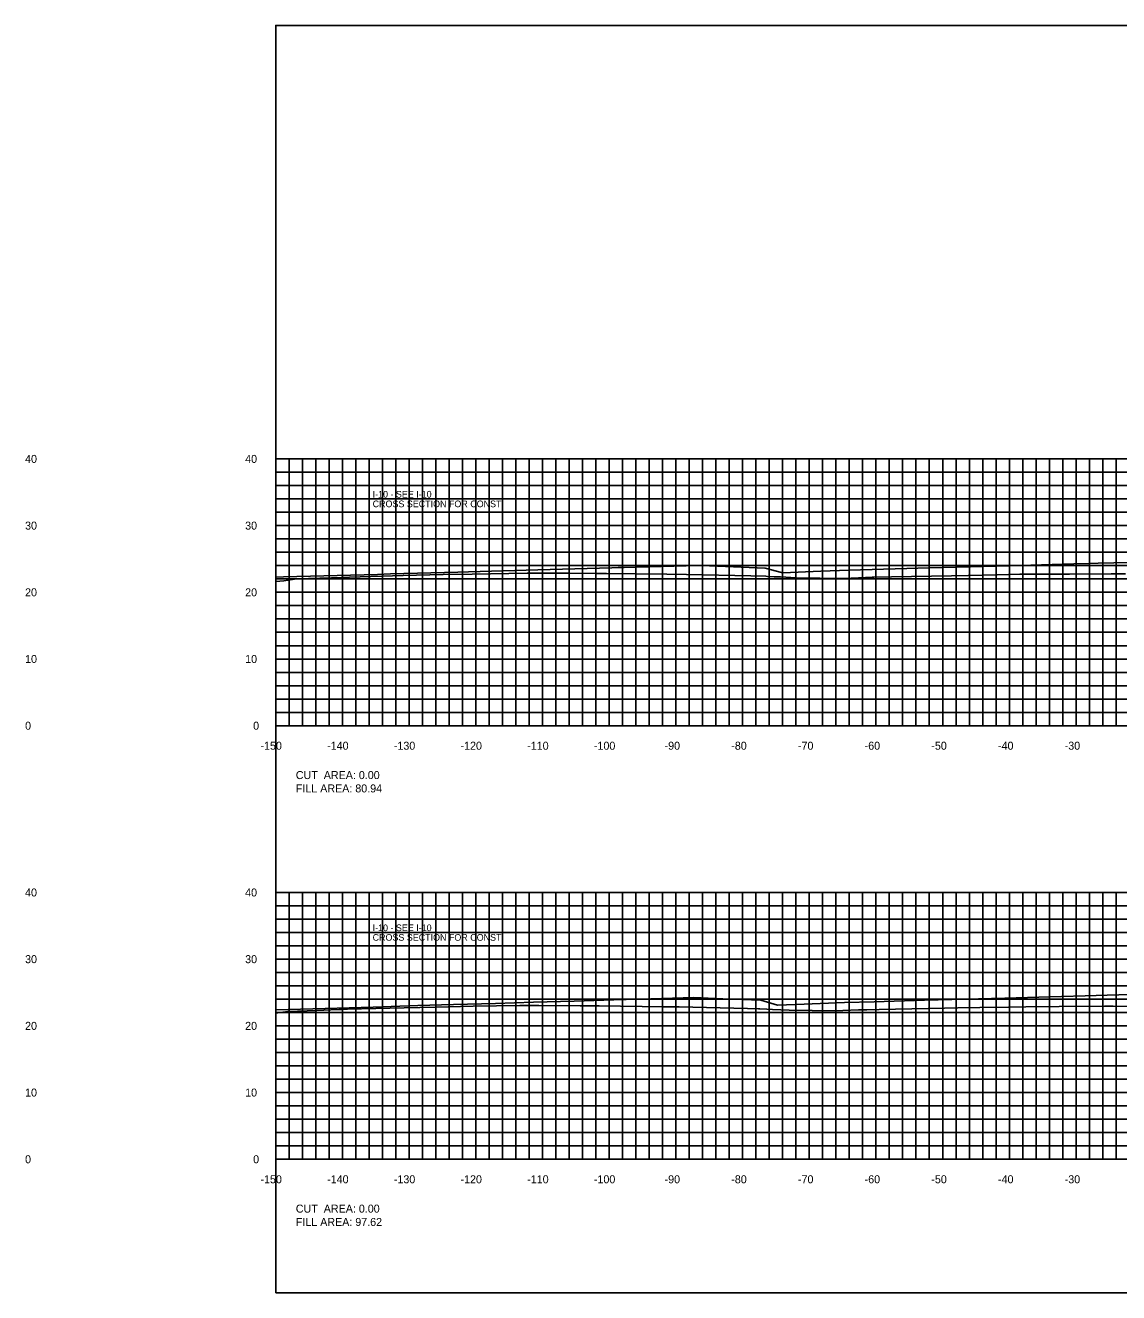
# Model space of a CAD drawing. Extents: x 1797652 to 1804145, y 245981 to 250269.
# Drawn here: x 1803803.4 to 1803967.4, y 250079.4 to 250269.4 of the extents above; entities that cross this region are included whole.
import ezdxf

# ---------------------------------------------------------------- set-up
doc = ezdxf.new("R2010")
doc.units = 0
for name, color, linetype in [('10', 7, 'Continuous'), ('3', 7, 'Continuous'), ('31', 7, 'Continuous'), ('60', 7, 'Continuous'), ('ANNO-TXT', 7, 'Continuous'), ('CL-CNST', 7, 'Continuous'), ('Level 62', 7, 'Continuous'), ('M-ROADS', 7, 'Continuous')]:
    doc.layers.add(name, color=color, linetype=linetype)

msp = doc.modelspace()

# ---------------------------------------------------------------- linework, layer by layer
msp.add_lwpolyline([(1803841, 250079.43), (1804141, 250079.43), (1804141, 250269.43), (1803841, 250269.43)], close=True)
at = {"layer": '60'}
for p, q in [((1803840.94, 250204.43), (1803841, 250204.43)), ((1803841, 250164.43), (1803841, 250204.43)), ((1803840.94, 250194.43), (1803841, 250194.43)), ((1803840.94, 250184.43), (1803841, 250184.43)), ((1803840.94, 250174.43), (1803841, 250174.43)), ((1803840.94, 250164.43), (1803841, 250164.43)), ((1803841, 250164.43), (1804141, 250164.43)), ((1803841, 250164.37), (1803841, 250164.43)), ((1803851, 250164.37), (1803851, 250164.43)), ((1803861, 250164.37), (1803861, 250164.43)), ((1803871, 250164.37), (1803871, 250164.43)), ((1803881, 250164.37), (1803881, 250164.43)), ((1803891, 250164.37), (1803891, 250164.43)), ((1803901, 250164.37), (1803901, 250164.43)), ((1803911, 250164.37), (1803911, 250164.43)), ((1803921, 250164.37), (1803921, 250164.43)), ((1803931, 250164.37), (1803931, 250164.43)), ((1803941, 250164.37), (1803941, 250164.43)), ((1803951, 250164.37), (1803951, 250164.43)), ((1803961, 250164.37), (1803961, 250164.43)), ((1803840.94, 250139.43), (1803841, 250139.43)), ((1803841, 250099.43), (1803841, 250139.43)), ((1803840.94, 250129.43), (1803841, 250129.43)), ((1803840.94, 250119.43), (1803841, 250119.43)), ((1803840.94, 250109.43), (1803841, 250109.43)), ((1803840.94, 250099.43), (1803841, 250099.43)), ((1803841, 250099.43), (1804141, 250099.43)), ((1803841, 250099.37), (1803841, 250099.43)), ((1803851, 250099.37), (1803851, 250099.43)), ((1803861, 250099.37), (1803861, 250099.43)), ((1803871, 250099.37), (1803871, 250099.43)), ((1803881, 250099.37), (1803881, 250099.43)), ((1803891, 250099.37), (1803891, 250099.43)), ((1803901, 250099.37), (1803901, 250099.43)), ((1803911, 250099.37), (1803911, 250099.43)), ((1803921, 250099.37), (1803921, 250099.43)), ((1803931, 250099.37), (1803931, 250099.43)), ((1803941, 250099.37), (1803941, 250099.43)), ((1803951, 250099.37), (1803951, 250099.43)), ((1803961, 250099.37), (1803961, 250099.43))]:
    msp.add_line(p, q, dxfattribs=at)
at = {"layer": 'CL-CNST'}
for points in [[(1803841, 250186.69), (1803842.17, 250186.73), (1803856.27, 250187.12), (1803858.22, 250187.18), (1803868.29, 250187.46), (1803869.89, 250187.51), (1803880.31, 250187.8), (1803891.39, 250188.11), (1803892.34, 250188.14), (1803893.23, 250188.17), (1803904.36, 250188.47), (1803904.81, 250188.45), (1803914.38, 250188.06), (1803916.85, 250187.38), (1803916.89, 250187.36), (1803917.03, 250187.37), (1803922.74, 250187.59), (1803926.91, 250187.75), (1803935.63, 250188), (1803938.93, 250188.09), (1803945.19, 250188.26), (1803950.95, 250188.41), (1803960.69, 250188.68), (1803962.98, 250188.74), (1803964.33, 250188.78), (1803969, 250188.9)], [(1803841, 250121.82), (1803848.41, 250122.05), (1803855.6, 250122.25), (1803862.29, 250122.46), (1803867.63, 250122.61), (1803873.94, 250122.8), (1803879.66, 250122.96), (1803885.76, 250123.13), (1803891.68, 250123.31), (1803897.24, 250123.48), (1803903.71, 250123.66), (1803908.05, 250123.49), (1803913.73, 250123.26), (1803915.21, 250122.85), (1803916.24, 250122.52), (1803920.24, 250122.68), (1803926.26, 250122.91), (1803930.72, 250123.05), (1803938.29, 250123.26), (1803942.37, 250123.38), (1803950.32, 250123.6), (1803958.8, 250123.83), (1803962.35, 250123.94), (1803965.67, 250124.04), (1803974.37, 250124.28)]]:
    msp.add_lwpolyline(points, dxfattribs=at)
at = {"layer": 'Level 62'}
for p, q in [((1803841, 250204.43), (1804141, 250204.43)), ((1803841, 250164.43), (1803841, 250204.43)), ((1803843, 250164.43), (1803843, 250204.43)), ((1803845, 250164.43), (1803845, 250204.43)), ((1803847, 250164.43), (1803847, 250204.43)), ((1803849, 250164.43), (1803849, 250204.43)), ((1803851, 250164.43), (1803851, 250204.43)), ((1803853, 250164.43), (1803853, 250204.43)), ((1803855, 250164.43), (1803855, 250204.43)), ((1803857, 250164.43), (1803857, 250204.43)), ((1803859, 250164.43), (1803859, 250204.43)), ((1803861, 250164.43), (1803861, 250204.43)), ((1803863, 250164.43), (1803863, 250204.43)), ((1803865, 250164.43), (1803865, 250204.43)), ((1803867, 250164.43), (1803867, 250204.43)), ((1803869, 250164.43), (1803869, 250204.43)), ((1803871, 250164.43), (1803871, 250204.43)), ((1803873, 250164.43), (1803873, 250204.43)), ((1803875, 250164.43), (1803875, 250204.43)), ((1803877, 250164.43), (1803877, 250204.43)), ((1803879, 250164.43), (1803879, 250204.43)), ((1803881, 250164.43), (1803881, 250204.43)), ((1803883, 250164.43), (1803883, 250204.43)), ((1803885, 250164.43), (1803885, 250204.43)), ((1803887, 250164.43), (1803887, 250204.43)), ((1803889, 250164.43), (1803889, 250204.43)), ((1803891, 250164.43), (1803891, 250204.43)), ((1803893, 250164.43), (1803893, 250204.43)), ((1803895, 250164.43), (1803895, 250204.43)), ((1803897, 250164.43), (1803897, 250204.43)), ((1803899, 250164.43), (1803899, 250204.43)), ((1803901, 250164.43), (1803901, 250204.43)), ((1803903, 250164.43), (1803903, 250204.43)), ((1803905, 250164.43), (1803905, 250204.43)), ((1803907, 250164.43), (1803907, 250204.43)), ((1803909, 250164.43), (1803909, 250204.43)), ((1803911, 250164.43), (1803911, 250204.43)), ((1803913, 250164.43), (1803913, 250204.43)), ((1803915, 250164.43), (1803915, 250204.43)), ((1803917, 250164.43), (1803917, 250204.43)), ((1803919, 250164.43), (1803919, 250204.43)), ((1803921, 250164.43), (1803921, 250204.43)), ((1803923, 250164.43), (1803923, 250204.43)), ((1803925, 250164.43), (1803925, 250204.43)), ((1803927, 250164.43), (1803927, 250204.43)), ((1803929, 250164.43), (1803929, 250204.43)), ((1803931, 250164.43), (1803931, 250204.43)), ((1803933, 250164.43), (1803933, 250204.43)), ((1803935, 250164.43), (1803935, 250204.43)), ((1803937, 250164.43), (1803937, 250204.43)), ((1803939, 250164.43), (1803939, 250204.43)), ((1803941, 250164.43), (1803941, 250204.43)), ((1803943, 250164.43), (1803943, 250204.43)), ((1803945, 250164.43), (1803945, 250204.43)), ((1803947, 250164.43), (1803947, 250204.43)), ((1803949, 250164.43), (1803949, 250204.43)), ((1803951, 250164.43), (1803951, 250204.43)), ((1803953, 250164.43), (1803953, 250204.43)), ((1803955, 250164.43), (1803955, 250204.43)), ((1803957, 250164.43), (1803957, 250204.43)), ((1803959, 250164.43), (1803959, 250204.43)), ((1803961, 250164.43), (1803961, 250204.43)), ((1803963, 250164.43), (1803963, 250204.43)), ((1803965, 250164.43), (1803965, 250204.43)), ((1803967, 250164.43), (1803967, 250204.43)), ((1803841, 250202.43), (1804141, 250202.43)), ((1803841, 250200.43), (1804141, 250200.43)), ((1803841, 250198.43), (1804141, 250198.43)), ((1803841, 250196.43), (1804141, 250196.43)), ((1803841, 250194.43), (1804141, 250194.43)), ((1803841, 250192.43), (1804141, 250192.43)), ((1803841, 250190.43), (1804141, 250190.43)), ((1803841, 250188.43), (1804141, 250188.43)), ((1803841, 250186.43), (1804141, 250186.43)), ((1803841, 250184.43), (1804141, 250184.43)), ((1803841, 250182.43), (1804141, 250182.43)), ((1803841, 250180.43), (1804141, 250180.43)), ((1803841, 250178.43), (1804141, 250178.43)), ((1803841, 250176.43), (1804141, 250176.43)), ((1803841, 250174.43), (1804141, 250174.43)), ((1803841, 250172.43), (1804141, 250172.43)), ((1803841, 250170.43), (1804141, 250170.43)), ((1803841, 250168.43), (1804141, 250168.43)), ((1803841, 250166.43), (1804141, 250166.43)), ((1803841, 250164.43), (1804141, 250164.43)), ((1803841, 250139.43), (1804141, 250139.43)), ((1803841, 250099.43), (1803841, 250139.43)), ((1803843, 250099.43), (1803843, 250139.43)), ((1803845, 250099.43), (1803845, 250139.43)), ((1803847, 250099.43), (1803847, 250139.43)), ((1803849, 250099.43), (1803849, 250139.43)), ((1803851, 250099.43), (1803851, 250139.43)), ((1803853, 250099.43), (1803853, 250139.43)), ((1803855, 250099.43), (1803855, 250139.43)), ((1803857, 250099.43), (1803857, 250139.43)), ((1803859, 250099.43), (1803859, 250139.43)), ((1803861, 250099.43), (1803861, 250139.43)), ((1803863, 250099.43), (1803863, 250139.43)), ((1803865, 250099.43), (1803865, 250139.43)), ((1803867, 250099.43), (1803867, 250139.43)), ((1803869, 250099.43), (1803869, 250139.43)), ((1803871, 250099.43), (1803871, 250139.43)), ((1803873, 250099.43), (1803873, 250139.43)), ((1803875, 250099.43), (1803875, 250139.43)), ((1803877, 250099.43), (1803877, 250139.43)), ((1803879, 250099.43), (1803879, 250139.43)), ((1803881, 250099.43), (1803881, 250139.43)), ((1803883, 250099.43), (1803883, 250139.43)), ((1803885, 250099.43), (1803885, 250139.43)), ((1803887, 250099.43), (1803887, 250139.43)), ((1803889, 250099.43), (1803889, 250139.43)), ((1803891, 250099.43), (1803891, 250139.43)), ((1803893, 250099.43), (1803893, 250139.43)), ((1803895, 250099.43), (1803895, 250139.43)), ((1803897, 250099.43), (1803897, 250139.43)), ((1803899, 250099.43), (1803899, 250139.43)), ((1803901, 250099.43), (1803901, 250139.43)), ((1803903, 250099.43), (1803903, 250139.43)), ((1803905, 250099.43), (1803905, 250139.43)), ((1803907, 250099.43), (1803907, 250139.43)), ((1803909, 250099.43), (1803909, 250139.43)), ((1803911, 250099.43), (1803911, 250139.43)), ((1803913, 250099.43), (1803913, 250139.43)), ((1803915, 250099.43), (1803915, 250139.43)), ((1803917, 250099.43), (1803917, 250139.43)), ((1803919, 250099.43), (1803919, 250139.43)), ((1803921, 250099.43), (1803921, 250139.43)), ((1803923, 250099.43), (1803923, 250139.43)), ((1803925, 250099.43), (1803925, 250139.43)), ((1803927, 250099.43), (1803927, 250139.43)), ((1803929, 250099.43), (1803929, 250139.43)), ((1803931, 250099.43), (1803931, 250139.43)), ((1803933, 250099.43), (1803933, 250139.43)), ((1803935, 250099.43), (1803935, 250139.43)), ((1803937, 250099.43), (1803937, 250139.43)), ((1803939, 250099.43), (1803939, 250139.43)), ((1803941, 250099.43), (1803941, 250139.43)), ((1803943, 250099.43), (1803943, 250139.43)), ((1803945, 250099.43), (1803945, 250139.43)), ((1803947, 250099.43), (1803947, 250139.43)), ((1803949, 250099.43), (1803949, 250139.43)), ((1803951, 250099.43), (1803951, 250139.43)), ((1803953, 250099.43), (1803953, 250139.43)), ((1803955, 250099.43), (1803955, 250139.43)), ((1803957, 250099.43), (1803957, 250139.43)), ((1803959, 250099.43), (1803959, 250139.43)), ((1803961, 250099.43), (1803961, 250139.43)), ((1803963, 250099.43), (1803963, 250139.43)), ((1803965, 250099.43), (1803965, 250139.43)), ((1803967, 250099.43), (1803967, 250139.43)), ((1803841, 250137.43), (1804141, 250137.43)), ((1803841, 250135.43), (1804141, 250135.43)), ((1803841, 250133.43), (1804141, 250133.43)), ((1803841, 250131.43), (1804141, 250131.43)), ((1803841, 250129.43), (1804141, 250129.43)), ((1803841, 250127.43), (1804141, 250127.43)), ((1803841, 250125.43), (1804141, 250125.43)), ((1803841, 250123.43), (1804141, 250123.43)), ((1803841, 250121.43), (1804141, 250121.43)), ((1803841, 250119.43), (1804141, 250119.43)), ((1803841, 250117.43), (1804141, 250117.43)), ((1803841, 250115.43), (1804141, 250115.43)), ((1803841, 250113.43), (1804141, 250113.43)), ((1803841, 250111.43), (1804141, 250111.43)), ((1803841, 250109.43), (1804141, 250109.43)), ((1803841, 250107.43), (1804141, 250107.43)), ((1803841, 250105.43), (1804141, 250105.43)), ((1803841, 250103.43), (1804141, 250103.43)), ((1803841, 250101.43), (1804141, 250101.43)), ((1803841, 250099.43), (1804141, 250099.43))]:
    msp.add_line(p, q, dxfattribs=at)
at = {"layer": 'M-ROADS'}
for points in [[(1803841, 250186.04), (1803842.19, 250186.17), (1803844.14, 250186.46), (1803849.37, 250186.62), (1803850.8, 250186.67), (1803850.95, 250186.67), (1803852.05, 250186.72), (1803860.1, 250186.93), (1803866.1, 250187.08), (1803870.46, 250187.16), (1803878.68, 250187.32), (1803880.35, 250187.31), (1803885.05, 250187.29), (1803889.12, 250187.27), (1803890.58, 250187.27), (1803899.63, 250187.13), (1803902.58, 250187.09), (1803912.21, 250186.88), (1803914.48, 250186.83), (1803914.71, 250186.82), (1803915.73, 250186.77), (1803916.7, 250186.73), (1803919.05, 250186.58), (1803922.57, 250186.56), (1803925.92, 250186.51), (1803927.27, 250186.57), (1803929.44, 250186.65), (1803930.42, 250186.69), (1803930.69, 250186.7), (1803933.35, 250186.75), (1803942.31, 250186.92), (1803944.83, 250186.96), (1803949.18, 250187.06), (1803952.57, 250187.13), (1803954.53, 250187.16), (1803960.01, 250187.16), (1803966.28, 250187.21), (1803968.4, 250187.18)], [(1803841, 250121.37), (1803841.29, 250121.4), (1803842.8, 250121.59), (1803847.15, 250121.74), (1803849.27, 250121.81), (1803850.46, 250121.89), (1803850.53, 250121.89), (1803850.97, 250121.9), (1803851.76, 250121.92), (1803860.25, 250122.12), (1803864.96, 250122.25), (1803870.6, 250122.36), (1803877.58, 250122.49), (1803880.45, 250122.48), (1803886.66, 250122.44), (1803888.58, 250122.43), (1803889.48, 250122.43), (1803899.14, 250122.29), (1803901.49, 250122.26), (1803911.74, 250122.02), (1803913.39, 250121.98), (1803913.57, 250121.97), (1803914.65, 250121.94), (1803915.47, 250121.9), (1803918, 250121.77), (1803921.43, 250121.73), (1803924.86, 250121.69), (1803926.04, 250121.72), (1803928.38, 250121.81), (1803928.62, 250121.82), (1803929.63, 250121.85), (1803931.47, 250121.89), (1803941.29, 250122.08), (1803943.28, 250122.12), (1803946.56, 250122.17), (1803950.87, 250122.25), (1803953.47, 250122.3), (1803958.47, 250122.34), (1803965.26, 250122.39), (1803966.58, 250122.36), (1803977.43, 250122.19)]]:
    msp.add_lwpolyline(points, dxfattribs=at)

# ---------------------------------------------------------------- texts
at = {"layer": '10'}
for s, p in [('-150', (1803838.7, 250160.83)), ('-140', (1803848.7, 250160.83)), ('-130', (1803858.7, 250160.83)), ('-120', (1803868.7, 250160.83)), ('-110', (1803878.7, 250160.83)), ('-100', (1803888.7, 250160.83)), ('-90', (1803899.3, 250160.83)), ('-80', (1803909.3, 250160.83)), ('-70', (1803919.3, 250160.83)), ('-60', (1803929.3, 250160.83)), ('-50', (1803939.3, 250160.83)), ('-40', (1803949.3, 250160.83)), ('-30', (1803959.3, 250160.83)), ('-150', (1803838.7, 250095.83)), ('-140', (1803848.7, 250095.83)), ('-130', (1803858.7, 250095.83)), ('-120', (1803868.7, 250095.83)), ('-110', (1803878.7, 250095.83)), ('-100', (1803888.7, 250095.83)), ('-90', (1803899.3, 250095.83)), ('-80', (1803909.3, 250095.83)), ('-70', (1803919.3, 250095.83)), ('-60', (1803929.3, 250095.83)), ('-50', (1803939.3, 250095.83)), ('-40', (1803949.3, 250095.83)), ('-30', (1803959.3, 250095.83))]:
    msp.add_text(s, height=1.2, dxfattribs=at).set_placement(p)
at = {"layer": '3'}
for s, p in [('I-10 - SEE I-10', (1803855.52, 250198.63)), ('CROSS SECTION FOR CONST ', (1803855.52, 250197.19)), ('CROSS SECTION FOR CONST ', (1803855.52, 250132.19)), ('I-10 - SEE I-10', (1803855.52, 250133.63))]:
    msp.add_text(s, height=1, dxfattribs=at).set_placement(p)
at = {"layer": '31'}
for s, p in [('40', (1803803.4, 250203.83)), ('40', (1803836.4, 250203.83)), ('30', (1803803.4, 250193.83)), ('30', (1803836.4, 250193.83)), ('20', (1803803.4, 250183.83)), ('20', (1803836.4, 250183.83)), ('10', (1803803.4, 250173.83)), ('10', (1803836.4, 250173.83)), ('0', (1803803.4, 250163.83)), ('0', (1803837.6, 250163.83)), ('40', (1803803.4, 250138.83)), ('40', (1803836.4, 250138.83)), ('30', (1803803.4, 250128.83)), ('30', (1803836.4, 250128.83)), ('20', (1803803.4, 250118.83)), ('20', (1803836.4, 250118.83)), ('10', (1803803.4, 250108.83)), ('10', (1803836.4, 250108.83)), ('0', (1803803.4, 250098.83)), ('0', (1803837.6, 250098.83))]:
    msp.add_text(s, height=1.2, dxfattribs=at).set_placement(p)
at = {"layer": '60'}
for p in [(1803841, 250164.43), (1803841, 250099.43)]:
    msp.add_text('-', height=0.0001, dxfattribs=at).set_placement(p)
at = {"layer": 'ANNO-TXT'}
for s, p in [('CUT  AREA: 0.00', (1803844, 250156.43)), ('FILL AREA: 80.94', (1803844, 250154.43)), ('CUT  AREA: 0.00', (1803844, 250091.43)), ('FILL AREA: 97.62', (1803844, 250089.43))]:
    msp.add_text(s, height=1.2, dxfattribs=at).set_placement(p)

doc.saveas('drawing.dxf')
